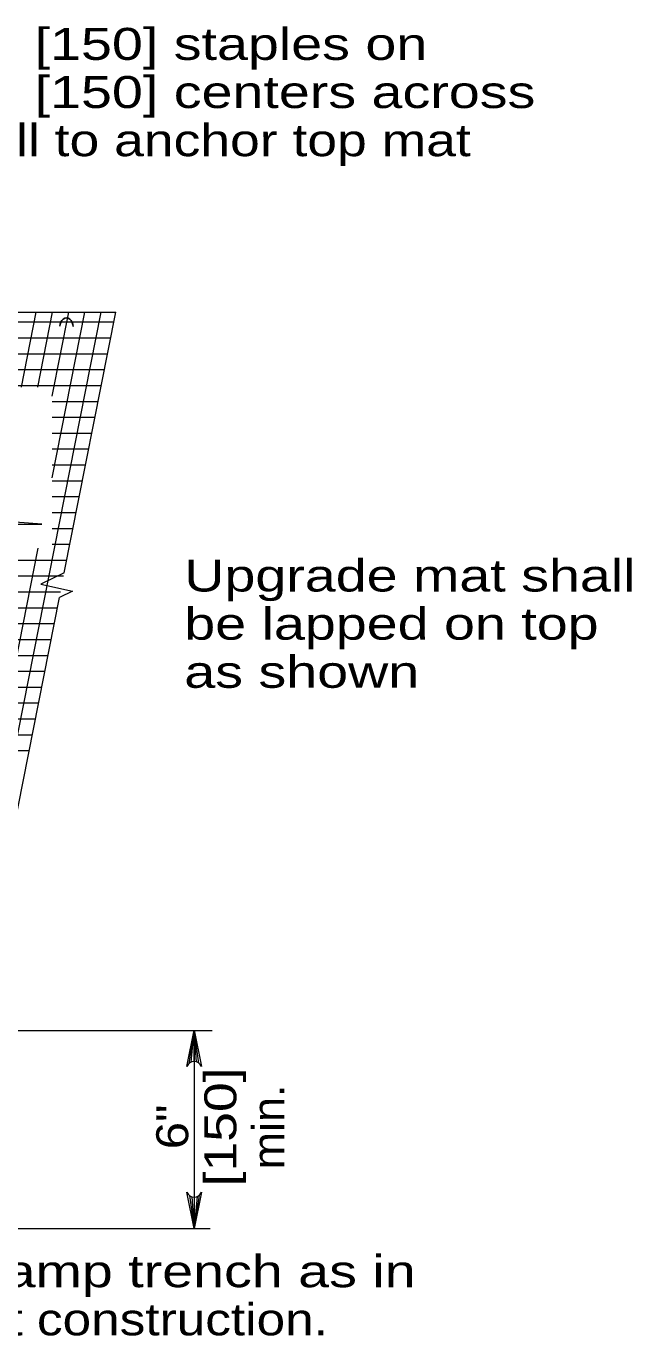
# Model space of a CAD drawing. Extents: x 1083.1 to 1117.1, y 719.4 to 741.4.
# Drawn here: x 1093.72 to 1096.67, y 725.93 to 732.31 of the extents above; entities that cross this region are included whole.
import ezdxf
from ezdxf.enums import TextEntityAlignment as Align

# ---------------------------------------------------------------- set-up
doc = ezdxf.new("R2010")
doc.units = 0
doc.header["$LTSCALE"] = 0.062
doc.layers.add('1', color=7, linetype='Continuous', lineweight=13)

msp = doc.modelspace()

# ---------------------------------------------------------------- linework, layer by layer
at = {"layer": '1'}
for p, q in [((1088.48358, 730.91883), (1094.15567, 730.91883)), ((1093.41692, 727.54358), (1094.08408, 730.91883)), ((1093.69642, 730.55367), (1093.7685, 730.91883)), ((1093.77525, 730.55367), (1093.84742, 730.91883)), ((1093.84542, 730.50967), (1093.92633, 730.91883)), ((1093.84542, 730.1105), (1094.00517, 730.91883)), ((1093.9045, 729.64783), (1094.15567, 730.91883)), ((1090.83675, 730.87075), (1094.14617, 730.87075)), ((1091.53717, 730.87075), (1094.14617, 730.87075)), ((1090.83675, 730.79333), (1094.13083, 730.79333)), ((1090.83675, 730.716), (1094.11567, 730.716)), ((1090.83675, 730.63858), (1094.10033, 730.63858)), ((1090.83675, 730.56125), (1094.08508, 730.56125)), ((1093.84542, 730.48383), (1094.06975, 730.48383)), ((1093.84542, 730.4065), (1094.05442, 730.4065)), ((1093.84542, 730.32908), (1094.03917, 730.32908)), ((1093.84542, 730.25175), (1094.02383, 730.25175)), ((1093.84542, 730.17433), (1094.00858, 730.17433)), ((1093.84542, 730.097), (1093.99325, 730.097)), ((1093.84542, 730.01958), (1093.978, 730.01958)), ((1093.84542, 729.94225), (1093.96267, 729.94225)), ((1093.84542, 729.86483), (1093.94733, 729.86483)), ((1093.33808, 727.54358), (1093.77767, 729.76792)), ((1093.84542, 729.7875), (1093.93217, 729.7875)), ((1090.83675, 729.71017), (1093.91683, 729.71017)), ((1090.83675, 729.63275), (1093.90158, 729.63275)), ((1090.83675, 729.55542), (1093.88625, 729.55542)), ((1093.48858, 727.54358), (1093.88075, 729.52775)), ((1090.83675, 729.478), (1093.871, 729.478)), ((1090.83675, 729.40067), (1093.85567, 729.40067)), ((1090.83675, 729.32325), (1093.84033, 729.32325)), ((1090.83675, 729.24592), (1093.82508, 729.24592)), ((1088.13775, 729.1685), (1093.80975, 729.1685)), ((1090.83675, 729.09117), (1093.7945, 729.09117)), ((1090.83675, 729.01375), (1093.77917, 729.01375)), ((1091.47242, 728.93642), (1093.764, 728.93642)), ((1091.2125, 728.859), (1093.74867, 728.859)), ((1091.13742, 728.78167), (1093.73333, 728.78167)), ((1093.55217, 727.41833), (1094.62617, 727.41833)), ((1094.51308, 727.25725), (1094.53792, 727.41933)), ((1094.5235, 727.26333), (1094.53792, 727.41933)), ((1094.53792, 727.41933), (1094.53792, 726.45275)), ((1094.53792, 727.26617), (1094.53792, 727.41933)), ((1094.54925, 727.26458), (1094.53792, 727.41933)), ((1094.56033, 727.25908), (1094.53792, 727.41933)), ((1094.56267, 726.61492), (1094.53792, 726.45275)), ((1094.5155, 726.613), (1094.53792, 726.45275)), ((1094.52658, 726.60758), (1094.53792, 726.45275)), ((1094.55233, 726.60875), (1094.53792, 726.45275)), ((1094.53792, 726.60592), (1094.53792, 726.45275)), ((1090.97608, 726.45275), (1094.61633, 726.45275))]:
    msp.add_line(p, q, dxfattribs=at)
for points in [[(1092.0585, 729.88508), (1093.79467, 729.88508), (1092.97125, 729.94767), (1093.1425, 729.88767)], [(1093.9045, 729.64783), (1093.79067, 729.59275), (1093.94525, 729.55908), (1093.88075, 729.52775)], [(1094.5025, 727.24233), (1094.53792, 727.41933), (1094.57333, 727.24233)], [(1094.57333, 726.62975), (1094.53792, 726.45275), (1094.5025, 726.62975)]]:
    msp.add_lwpolyline(points, dxfattribs=at)
for centre, start, end in [((1094.53794, 727.22807), 22.08782, 157.91395), ((1094.53786, 726.64405), 202.08782, 337.91395)]:
    msp.add_arc(centre, 0.0382, start, end, dxfattribs=at)
at = {"layer": '1', "lineweight": 25}
msp.add_ellipse((1093.91508, 730.84917), major_axis=(0.00106, 0.04097), ratio=0.78812, start_param=4.7124002, end_param=7.8539929, dxfattribs=at)

# ---------------------------------------------------------------- texts
at = {"layer": '1'}
for s, width, p in [('6" [150] staples on', 1.3, (1093.43775, 732.148)), ('6" [150] centers across', 1.3, (1093.43775, 731.91333)), ('roll to anchor top mat', 1.25, (1093.43775, 731.67867)), ('Upgrade mat shall', 1.3, (1094.49, 729.557)), ('be lapped on top', 1.3, (1094.49, 729.32233)), ('as shown', 1.3, (1094.49, 729.08767)), ('Fill and tamp trench as in', 1.3, (1092.58883, 726.16642)), ('check slot construction.', 1.2, (1092.58883, 725.93175))]:
    msp.add_text(s, height=0.156, dxfattribs=dict(at, width=width)).set_placement(p)
for s, width, p in [('[150]', 1.25, (1094.744, 726.94767)), ('min.', 1.05, (1094.97867, 726.94767)), ('6"', 1.15, (1094.50933, 726.94767))]:
    msp.add_text(s, height=0.156, rotation=90, dxfattribs=dict(at, width=width)).set_placement(p, align=Align.CENTER)

doc.saveas('drawing.dxf')
